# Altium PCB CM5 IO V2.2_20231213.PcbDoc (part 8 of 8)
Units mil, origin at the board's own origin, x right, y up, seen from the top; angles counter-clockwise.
Board outline 6299.61 x 3544.09 mil, 4 copper layers (Top, GND, Power, Bottom), stack 35.4 mil thick; 482 components, 404 nets, 1857 pads, 2731 vias.
Unrouted connection lines stored in the file: 1872.
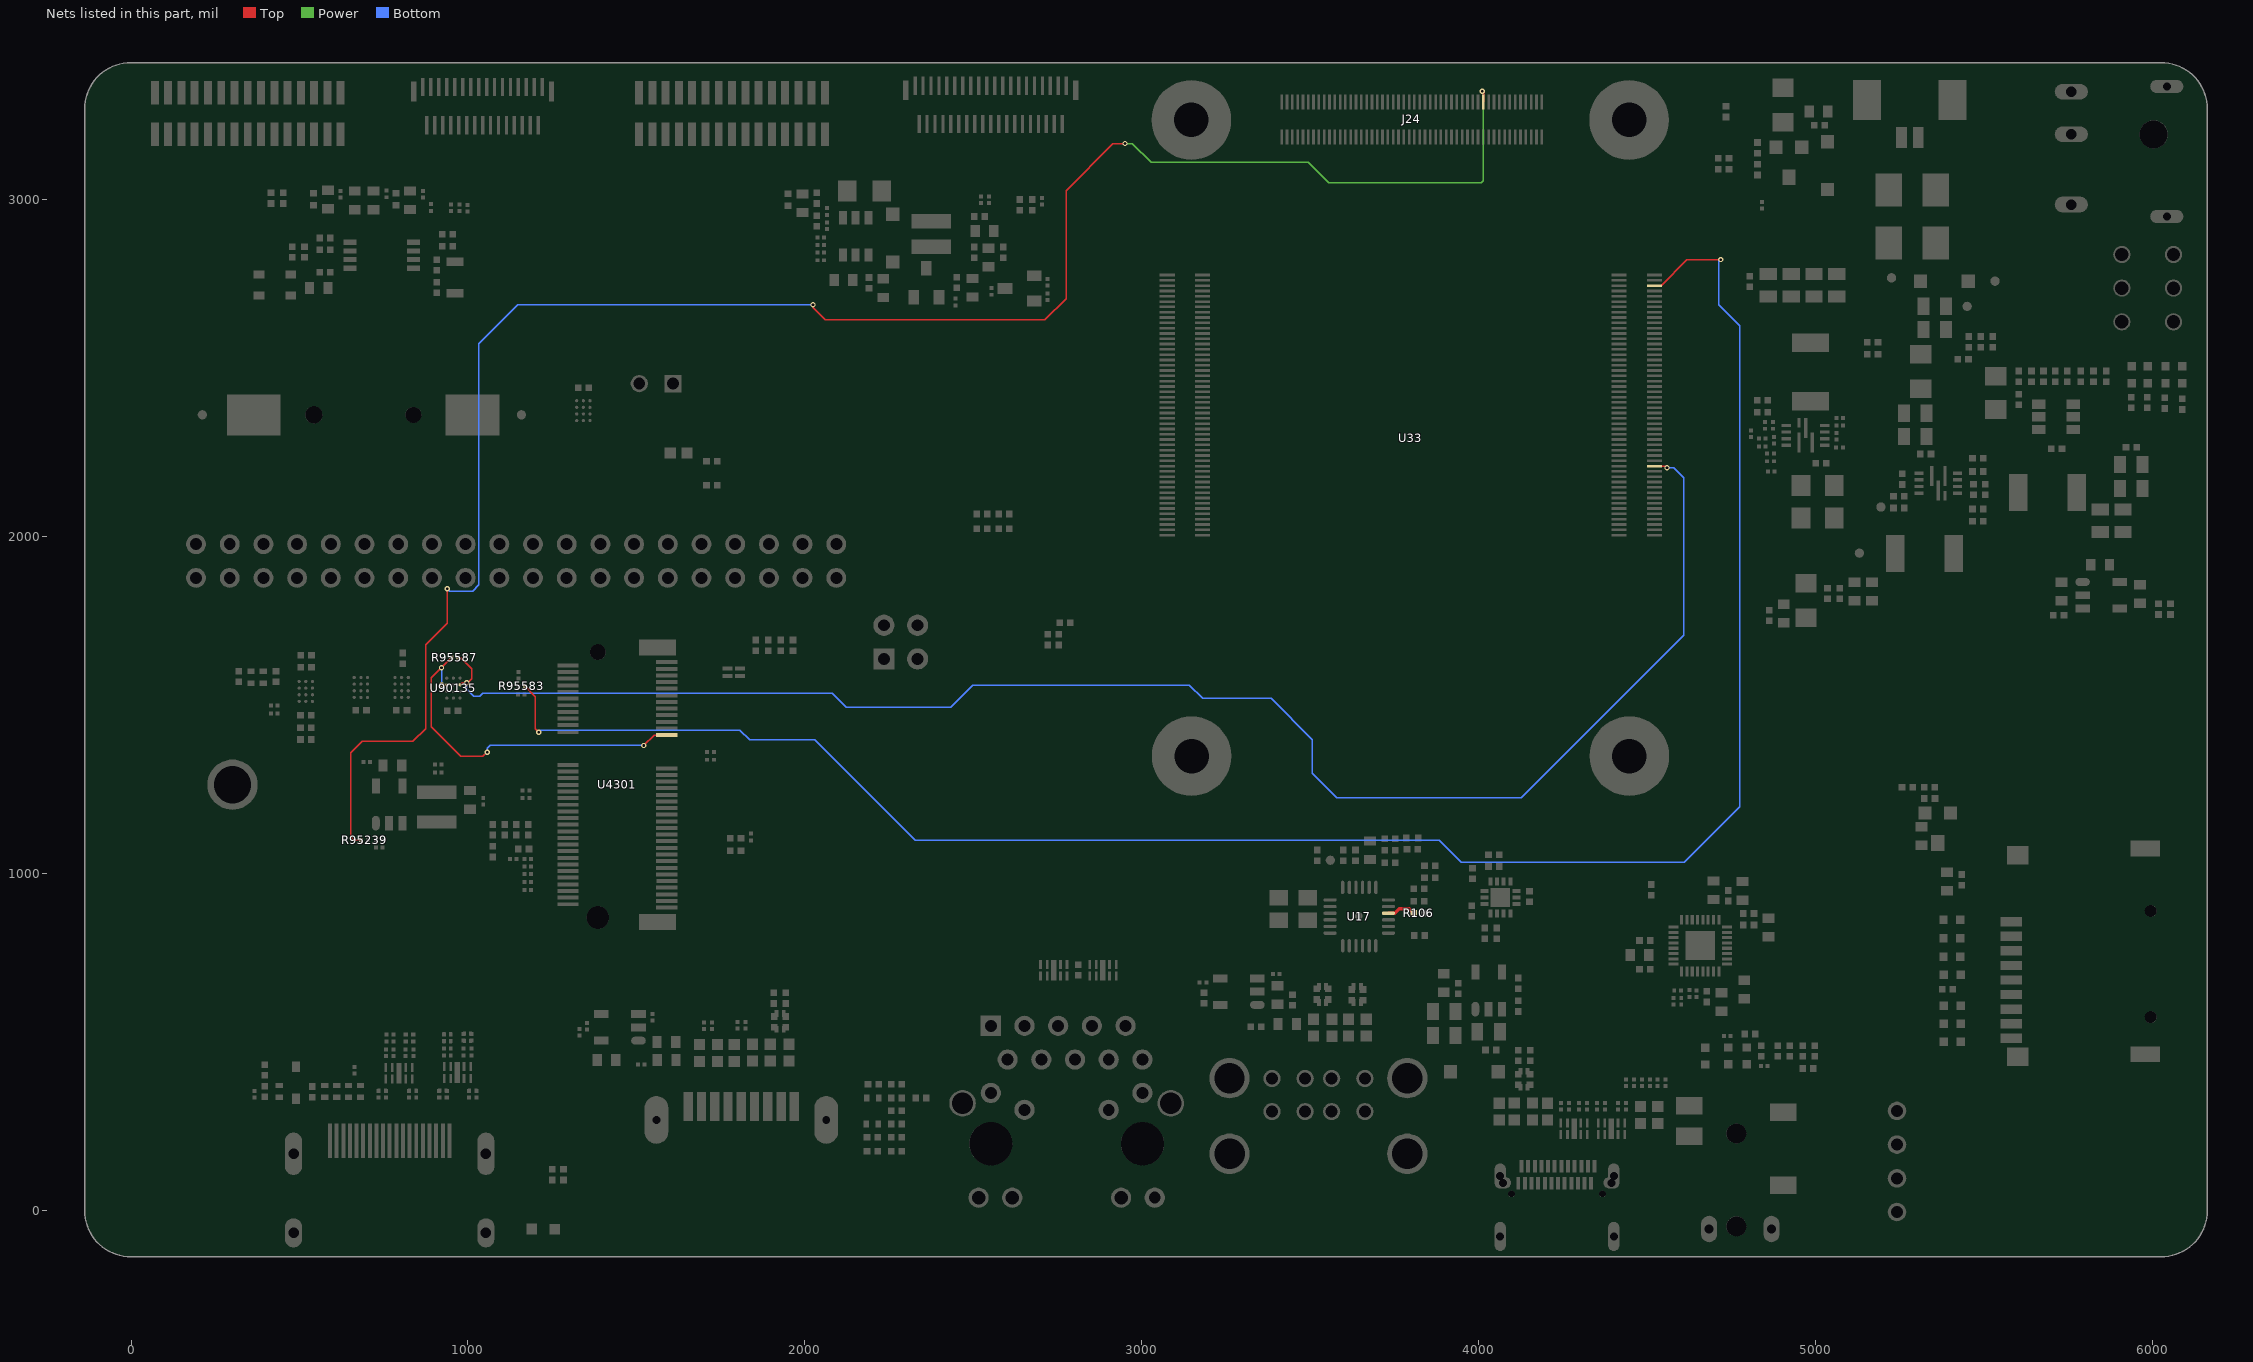
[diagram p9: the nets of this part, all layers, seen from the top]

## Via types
v1: diameter 15.75, hole 7.87, Top to Bottom, 2292 vias
v2: diameter 19.68, hole 11.81, Top to Bottom, 439 vias

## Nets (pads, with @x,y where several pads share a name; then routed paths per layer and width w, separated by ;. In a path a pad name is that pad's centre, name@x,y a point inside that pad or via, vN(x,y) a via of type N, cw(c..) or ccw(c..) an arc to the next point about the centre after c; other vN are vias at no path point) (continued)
WIFI_LED: R95583.1 U33.95 | length 5831.9
  Top w3.94: R95583.1@1169.29,1554.13 1199.8,1523.62 1199.8,1428.15 v1(1209.65,1418.31) ; U33.95@4520.47,2743.5 4540.35,2743.5 4616.73,2819.88 4717.52,2819.88 v1(4717.52,2820.87)
  Bottom w3.94: v1(1209.65,1418.31) 1215.55,1424.21 1807.09,1424.21 1835.63,1395.67 2029.53,1395.67 2327.76,1097.44 3882.87,1097.44 3947.83,1032.48 4609.25,1032.48 4774.61,1197.83 4774.61,2624.02 4711.61,2687.01 4711.61,2814.96 v1(4717.52,2820.87)
WIFI_PWR_EN: J24.24 R95239.1 | length 5608.1
  Top w3.94: R95239.1@683.07,1098.43 662.4,1098.43 652.76,1108.07 652.76,1357.98 686.5,1391.73 836.61,1391.73 874.02,1429.13 874.02,1678.15 937.99,1742.13 v1(937.99,1844.49) ; v1(2023.62,2687.01) 2023.93,2687.32 2023.93,2677.47 2059.67,2641.73 2711.61,2641.73 2774.61,2704.72 2774.61,3025.9 2914.06,3165.35 v1(2949.8,3165.35) ; v1(4009.84,3320.87) 4013.78,3316.93 4013.78,3289.17 J24.24@4013.19,3288.58
  Power w3.94: v1(2949.8,3165.35) 2971.26,3165.35 3027.36,3109.25 3494.04,3109.25 3554.08,3049.21 4006.89,3049.21 4012.8,3055.12 4012.8,3317.91 v1(4009.84,3320.87)
  Bottom w3.94: v1(937.99,1844.49) 945.87,1836.61 1013.78,1836.61 1032.48,1855.31 1032.48,2571.48 1148,2687.01 v1(2023.62,2687.01)
WIFI_REG_ON: R95587.2 U4301.23 U90135.B1 | length 1064.8
  Top w3.94: v1(921.26,1609.25) v1@921.26,1610.24 ; v1(922.24,1559.06) U90135.B1@937.01,1559.05 ; R95587.2@950.79,1639.76 v1@921.26,1610.24 ; v1(1057.09,1359.25) 1044.29,1346.46 978.35,1346.46 890.75,1434.06 890.75,1579.72 v1@921.26,1610.24 ; v1(1521.65,1378.94) 1552.52,1409.8 U4301.23@1589.78,1409.8
  Bottom w3.94: v1(921.26,1609.25) 922.24,1608.27 v1(922.24,1559.06) ; v1(1057.09,1359.25) 1057.09,1370.08 1065.94,1378.94 v1(1521.65,1378.94)
WIFI_REG_ON_E: R95587.1 U33.27 U90135.B3 | length 4783.4
  Top w3.94: R95587.1@970.47,1639.76 978.35,1639.76 1011.81,1606.3 1011.81,1576.77 998.03,1562.99 v1(996.06,1564.96) 982.29,1564.96 U90135.B3@976.38,1559.05 ; U33.27@4520.47,2208.07 4552.76,2208.07 v1(4558.07,2202.76)
  Bottom w3.94: v1(996.06,1564.96) 996.06,1546.26 1016.73,1525.59 1035.43,1525.59 1044.29,1534.45 2080.71,1534.45 2123.03,1492.13 2432.09,1492.13 2498.03,1558.07 3140.44,1558.07 3179.81,1518.7 3383.44,1518.7 3505.91,1396.23 3505.91,1295.95 3578.43,1223.43 4125.11,1223.43 4608.27,1706.58 4608.27,2173.03 4578.54,2202.76 v1(4558.07,2202.76)
XRSTJ: R106.2 U17.16 | length 86
  Top w9.84: U17.16@3731.49,881.2 3750.29,881.2 3763.78,894.68 3792.81,894.68 R106.2@3806.29,881.2
pads on no net: CN14A1.14 CN14A1.15 J3.21 J3.22 J6.16 J6.17 J6.18 J6.19 J6.20 J6.21 J6.22 J6.23 J6.24 J6.25 J6.26 J6.27 J6.28 J6.29 J6.30 J7.16 J7.17 J7.18 J7.19 J7.20 J7.21 J7.22 J7.23 J7.24 J7.25 J7.26 J7.27 J7.28 J7.29 J7.30 J15.1 J15.7 J15.8 J24.16 J24.33 J24.35 J24.39 J24.41 J24.44 J24.46 J24.50 J24.52 J24.54 J24.58 J24.60 J24.64 J24.66 J24.70 J24.78 J24.80 J24.82 J24.84 J24.86 J24.88 J24.91 J24.97 J5002.8 J5002.9 J5002.22 J5002.26 J8202.H1 J8202.H2 U1.4 U17.2 U17.22 U17.23 U17.24 U27.4 U27.12 U33.16 U33.18 U33.26 U33.64 U33.68 U33.70 U33.72 U33.76 U33.78 U33.94 U33.101 U33.104 U33.111 U33.143 U33.146 U33.148 U33.149 U33.152 U33.154 U33.158 U33.160 U33.164 U33.166 U37.6 U4301.8 U4301.9 U4301.10 U4301.11 U4301.12 U4301.13 U4301.14 U4301.15 U4301.16 U4301.17 U4301.19 U4301.22 U4301.32 U4301.34 U4301.36 U4301.38 U4301.40 U4301.44 U4301.46 U4301.48 U4301.59 U4301.61 U4301.62 U4301.64 U4301.65 U4301.66 U4301.67 U4301.68 U4301.71 U4301.73 U4301.78 U4301.79 U90104.5 U90104.36 U90104.37 U90129.11 U90129.29 U90129.30 U90131.3 U90131.4 U90133.D1 U90133.D3 U90135.A1 U90135.A3 U90136.C1 U90136.C3 U90136.D1 U90136.D3

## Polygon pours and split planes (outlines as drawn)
GND on Power (solid, remove dead copper, pour order 10): -163.39,1177.17 -163.39,1139.76 -110.24,1139.76 -110.24,1177.17
VCC5V0_SYS on Power (solid, remove dead copper, pour order 5): 4933.07,2027.56 4933.07,1174.21 4665.35,906.5 3097.44,906.5 2696.6,1307.33 2696.6,2641.73 2591.41,2746.92 2466.54,2746.92 2315.51,2595.9 1871.06,2595.9 1756.61,2710.35 856.3,2710.35 717.87,2848.78 717.87,2941.93 694.07,2965.73 629.92,2965.73 596.86,2932.67 478.35,2932.67 94.49,2548.81 94.49,592.72 433.17,254.04 2172.24,254.04 2213.48,295.28 3724.41,295.28 3728.35,291.34 4375,291.34 4706.19,-39.86 5350.39,-39.86 5435.77,45.52 5435.77,281.5 5776.57,625.39 5776.57,2027.56
VBUS5V0_TYPEC on Power (solid, remove dead copper, pour order 4): 4049.21,25.59 4049.21,-35.79 4286.77,-35.79 4307.79,-14.76 4307.79,15.47 4282.91,40.35 4282.91,59.61 4303.03,79.72 4303.03,156.37 4293.31,166.09 4267.96,166.09 4253.44,151.57 4253.44,38.2 4241.45,26.21 4220.1,26.21 4209.89,36.42 4209.89,141.98 4194.82,157.05 4182.58,157.11 4139.76,115.16 4139.76,42.32 4123.03,25.59
GND on Power (solid, remove dead copper, pour order 3): -235.24,3552.17 -235.24,-220.47 6285.43,-220.47 6285.43,3552.17
VCC3V3_SYS on Power (solid, remove dead copper, pour order 2): 2326.38,2866.14 2325.2,2866.14 2325.2,2785.04 2856.3,2785.04 2856.3,2854.33 2726.77,2983.86 2444.09,2983.86
VCC5V0_USB on Power (solid, remove dead copper, pour order 1): 3104.82,910.43 4664.37,910.43 4930.12,1176.18 4930.12,1758.86 4570.87,1758.86 4570.87,1324.8 4500,1253.94 3123.03,1253.94 3084.15,1215.06 3084.15,931.1
VCC3V3_SYS on Power (solid, remove dead copper, pour order 0): 5884.84,2038.39 5884.84,2382.87 5312.01,2382.87 4742.38,2952.5 3428.41,2952.5 3355.31,2879.41 2336.1,2879.41 2232.24,2775.54 2099.36,2775.54 1770.67,3104.24 494.19,3104.24 465.74,3075.79 465.74,2967.71 484.25,2949.2 597.06,2949.2 621.06,2973.19 704.49,2973.19 731.82,2945.87 731.82,2856.82 869.09,2719.55 1767.78,2719.55 1883.86,2603.47 2318.77,2603.47 2471.46,2756.15 2615.4,2756.15 2684.06,2687.5 3517.22,2687.5 4166.34,2038.39
GND on GND (solid, remove dead copper, pour order 6): -155.51,3423.23 -155.51,-629.92 6181.1,-629.92 6181.1,3423.23
GND on Bottom (solid, remove dead copper, pour order 9): -171.26,3438.98 -171.26,-629.92 6196.85,-629.92 6196.85,3438.98
VBUS5V0_TYPEC on Bottom (solid, remove dead copper, pour order 7): 4049.21,25.59 4049.21,-35.79 4286.77,-35.79 4307.79,-14.76 4307.79,15.47 4282.91,40.35 4282.91,59.61 4303.03,79.72 4303.03,156.37 4293.31,166.09 4267.96,166.09 4253.44,151.57 4253.44,38.2 4241.45,26.21 4220.1,26.21 4209.89,36.42 4209.89,141.98 4194.82,157.05 4182.58,157.11 4139.76,115.16 4139.76,42.32 4123.03,25.59
GND on Top (solid, remove dead copper, pour order 8): -147.64,3415.35 -147.64,-629.92 6173.23,-629.92 6173.23,3415.35

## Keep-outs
Top:
  region: 494.09,1573.82 494.09,1504.92 543.31,1504.92 543.31,1573.82 494.09,1573.82
  region: 3371.06,954.72 3371.06,827.76 3524.61,827.76 3524.61,954.72 3371.06,954.72
  region: 935.04,2827.76 935.04,2707.68 987.2,2707.68 987.2,2827.76 935.04,2827.76
  region: 657.48,1585.63 657.48,1516.73 706.69,1516.73 706.69,1585.63 657.48,1585.63
  region: 4178.15,3263.78 4178.15,3312.01 3420.28,3312.01 3420.28,3263.78 4178.15,3263.78
  region: 2315.94,2956.69 2315.94,2837.6 2434.06,2837.6 2434.06,2956.69 2315.94,2956.69
  region: 4882.87,2553.15 4882.87,2422.24 5082.68,2422.24 5082.68,2553.15 4882.87,2553.15
  region: 3422.24,3208.66 3422.24,3160.43 4178.15,3160.43 4178.15,3208.66 3422.24,3208.66
  region: 5173.23,2971.46 5173.23,2921.26 5412.4,2921.26 5412.4,2971.46 5173.23,2971.46
  region: 4440.94,2009.84 4440.94,2780.51 4390.75,2780.51 4390.75,2009.84 4440.94,2009.84
  region: 932.09,1583.66 932.09,1514.76 981.3,1514.76 981.3,1583.66 932.09,1583.66
  region: 4496.06,2782.48 4496.06,2014.76 4545.28,2014.76 4545.28,2782.48 4496.06,2782.48
  region: 848.43,1256.89 848.43,1150.59 966.54,1150.59 966.54,1256.89 848.43,1256.89
  region: 3051.18,2780.51 3051.18,1996.06 3100.39,1996.06 3100.39,2780.51 3051.18,2780.51
  region: 778.54,1585.63 778.54,1516.73 827.76,1516.73 827.76,1585.63 778.54,1585.63
  region: 5598.43,2230.31 5598.43,2028.54 5794.29,2028.54 5794.29,2230.31 5598.43,2230.31
  region: 1311.02,2413.39 1311.02,2331.69 1373.03,2331.69 1373.03,2413.39 1311.02,2413.39
  region: 3155.51,1995.08 3203.74,1995.08 3203.74,2777.56 3155.51,2777.56 3155.51,1995.08
  region: 5215.55,2050.2 5215.55,1848.43 5429.13,1848.43 5429.13,2050.2 5215.55,2050.2
Power:
  region: 1657.15,1500 ccw(c1645.67,1500) 1645.67,1511.48 ccw(c1645.67,1500) 1634.19,1500 ccw(c1645.67,1500) 1645.67,1488.52 ccw(c1645.67,1500)
  region: 5310.45,2305.12 ccw(c5297.24,2305.12) 5297.24,2318.32 ccw(c5297.24,2305.12) 5284.04,2305.12 ccw(c5297.24,2305.12) 5297.24,2291.91 ccw(c5297.24,2305.12)
Keep-Out Layer:
  lines w3.94: -53.15,-0.79 53.15,-0.79 ; -53.12,1929.12 53.18,1929.12 ; 242.15,177.15 348.45,177.15 ; 242.15,2893.68 348.45,2893.68 ; 2230.34,-0.02 2336.64,-0.02 ; 2230.34,1929.12 2336.64,1929.12 ; 5517.74,177.15 5624.04,177.15 ; 5517.74,2893.68 5624.04,2893.68 ; -137.8,-0.79 ccw(c0,-0.79) 0,-138.58 6024.02,-138.58 ccw(c6024.02,-0.79) 6161.81,-0.79 6161.81,3267.72 ccw(c6024.02,3267.72) 6024.02,3405.51 0,3405.51 ccw(c0,3267.72) -137.8,3267.72 -137.8,-0.79 ; 5971.46,3161.42 6033.46,3161.42 6033.46,3223.43 5971.46,3223.43 5971.46,3161.42

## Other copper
Top:
  region net N43540: 5859.25,3364.17 5529.53,3364.17 5486.22,3320.87 5486.22,3237.2 5383.86,3134.84 5212.6,3134.84 5178.4,3100.64 5178.4,2969.49 5499.02,2969.49 5694.88,3165.35 5694.88,3211.61 5717.77,3234.5 5859.25,3234.5 5859.25,3364.17
  region net VCC_SYSIN: 4778.54,2591.54 4778.54,2614.17 4749.02,2614.17 4749.02,2584.15 4755.41,2584.15 4762.8,2591.54 4778.54,2591.54
  region net VCC5V0_USB: 3153.54,625 3153.54,559.06 3257.87,559.06 3257.87,625 3153.54,625
  region net VCC3V3_SYS: 5750,2245.08 5750,2040.35 5932.09,2040.35 5932.09,2274.61 5779.53,2274.61 5750,2245.08
  region net GND: 3360.24,913.39 3407.48,913.39 3407.48,923.23 3360.24,923.23 3360.24,913.39
  region net N42228: 5361.22,2150.59 5329.23,2118.6 5329.23,2043.31 5369.83,2002.71 5369.83,1849.41 5476.38,1849.41 5490.16,1863.19 5490.16,2018.7 5467.52,2041.34 5467.52,2042.32 5441.44,2068.41 5441.44,2083.66 5429.87,2095.23 5374.02,2095.23 5365.53,2103.72 5365.53,2150.59 5361.22,2150.59
  region net VCC_LEDA: 2322.83,3270.67 2322.83,3160.43 2343.5,3160.43 2343.5,3250 2322.83,3270.67
  region net VCC5V0_SYS: 3874.02,728.35 3874.02,669.29 4000,669.29 4000,728.35 3874.02,728.35
  region net VCC5V0_SYS: 4050.2,1064.96 4050.2,1045.28 4106.3,1045.28 4106.3,1064.96 4050.2,1064.96
  region net VCC5V0_SYS: 2381.89,2698.82 2526.57,2698.82 2526.57,2743.11 2381.89,2743.11 2381.89,2698.82
  region net VCC_3V3_S3: 5070.87,2902.56 5097.44,2875.98 5103.35,2875.98 5124.02,2896.65 5124.02,2906.5 5099.41,2931.1 5070.87,2902.56
  region net N132478: 716.54,1269.68 709.65,1262.8 709.65,1254.92 717.03,1247.54 730.31,1247.54 730.31,1269.68 716.54,1269.68
  region net VCC5V0_SYS: 4876.97,2185.04 4825.3,2133.37 4825.3,1875 4863.44,1836.86 4958.66,1836.86 4958.66,2186.02 4876.97,2186.02 4876.97,2185.04
  region net VCC3V3_WF: 1375,1397.64 1354.33,1376.97 1354.33,1345.47 1371.56,1328.25 1399.61,1328.25 1399.61,1397.64 1375,1397.64
  region net VCC12V: 5292.57,2486.22 5292.57,2291.58 5356.79,2227.36 5356.79,2189.47 5380.91,2165.35 5380.91,2157.48 5398.5,2157.48 5398.5,2194.02 5408.46,2203.99 5438.73,2203.99 5502.95,2268.21 5560.53,2268.21 5635.83,2343.5 5679.13,2343.5 5679.13,2367.25 5638.9,2367.25 5603.35,2402.81 5521.9,2402.81 5483.76,2440.94 5483.76,2465.06 5462.6,2486.22 5292.57,2486.22
  region net VCC_MIPI: 1940.55,3004.72 2053.54,3004.72 2053.54,3042.91 1957.09,3042.91 1940.55,3026.38 1940.55,3004.72
  region net OVCJ: 3545.28,922.24 3545.28,918.31 3570.62,918.31 3570.62,922.98 3562.99,930.61 3553.64,930.61 3545.28,922.24
  region net VCC5V0_USB1: 1679.13,331.69 1679.13,243.11 1689.96,232.28 1696.85,232.28 1711.12,246.56 1711.12,257.87 1706.94,262.06 1706.94,331.69 1679.13,331.69
  region net VCC5V0_USB: 1325.79,519.68 1325.79,423.23 1408.46,423.23 1408.46,519.68 1325.79,519.68
  region net GND: 3497.05,861.22 3497.05,821.85 3506.89,821.85 3506.89,861.22 3497.05,861.22
  region net N16722445: 2176.18,2771.65 2176.18,2751.97 2199.8,2751.97 2199.8,2771.65 2176.18,2771.65
  region net VBUS5V0_TYPEC: 3850.39,458.66 3862.2,446.85 3872.05,446.85 3872.05,463.58 3850.39,463.58 3850.39,458.66
  region net VCC5V0_USB1: 1490.16,509.84 1490.16,467.52 1524.11,433.56 1563.98,433.56 1563.98,509.84 1490.16,509.84
  region net N43676: 5634.72,2323.82 5557.95,2247.05 5557.95,2033.34 5568.9,2022.39 5631.15,2022.39 5655.02,2046.26 5655.02,2212.11 5699.8,2256.89 5699.8,2323.82 5634.72,2323.82
  region net VCC5V0_SYS: 5169.29,2066.93 5162.4,2066.93 5162.4,2029.53 5184.55,2029.53 5184.55,2051.67 5169.29,2066.93
  region net N28976: 3691.93,941.93 3736.22,941.93 3762.8,968.5 3762.8,1091.54 3795.28,1091.54 3795.28,1121.06 3736.22,1121.06 3736.22,1011.81 3691.93,967.52 3691.93,941.93
  region net VCC5V0_USB: 3101.57,967.72 3056.69,967.72 3056.69,613.78 3120.47,550 3251.97,550 3251.97,616.54 3144.49,616.54 3101.57,659.45 3101.57,967.72
  region net VCC5V0_SYS: 4933.56,2301.18 4933.56,2260.33 4898.62,2225.39 4898.62,2213.58 4876.97,2191.93 4876.97,1835.63 5263.78,1835.63 5263.78,2055.73 5174.58,2055.73 5130.91,2012.06 5021.9,2012.06 5009.35,2024.61 5009.35,2210.14 4975.39,2244.09 4975.39,2279.53 4960.63,2279.53 4949.8,2290.35 4949.8,2301.18 4933.56,2301.18
  region net VCC_3V3_S3: 5293.31,1122.05 5368.11,1122.05 5368.11,1163.39 5337.11,1194.39 5293.31,1194.39 5293.31,1122.05
  region net VCC5V0_SYS: 641.73,2984.25 641.73,2937.01 682.09,2937.01 682.09,2984.25 641.73,2984.25
  region net VCC3V3_SYS: 520.67,2993.11 520.67,2952.76 554.13,2952.76 554.13,2993.11 520.67,2993.11
  region net VCC5V0_SYS: 4050.2,1064.96 4050.2,1004.92 4078.74,1004.92 4078.74,1064.96 4050.2,1064.96
  region net VCC_3V3_S0: 5731.3,1919.29 5731.3,1854.33 5830.71,1854.33 5830.71,1919.29 5731.3,1919.29
  region net VCC5V0_USB: 3812.01,1114.17 3812.01,1044.29 3850.39,1044.29 3850.39,1114.17 3812.01,1114.17
  region net VCC5V0_USB: 3077.76,968.11 3077.76,911.42 3180.12,911.42 3180.12,968.11 3077.76,968.11
  region net N16763522: 3321.11,624.02 3321.11,578.99 3346.95,553.15 3346.95,462.11 3369.09,439.96 3397.64,439.96 3434.06,476.38 3434.06,576.77 3455.71,598.43 3455.71,624.02 3321.11,624.02
  region net VCC3V3_SD: 5382.87,1113.19 5288.39,1113.19 5288.39,930.12 5456.69,930.12 5456.69,975.39 5350.39,975.39 5350.39,1051.18 5382.87,1051.18 5382.87,1113.19
  region net VCC12V: 5466.54,2490.16 5456.69,2490.16 5456.69,2466.54 5466.54,2466.54 5466.54,2490.16
  region net VCC3V3_WF: 1134.84,1279.53 1154.53,1279.53 1160.43,1285.43 1160.43,1302.17 1134.84,1302.17 1134.84,1279.53
  region net VCC5V0_SYS: 790.35,1342.52 790.35,1289.37 864.17,1289.37 864.17,1342.52 790.35,1342.52
  region net N132294: 802.17,1170.28 802.17,1126.97 966.54,1126.97 966.54,1170.28 802.17,1170.28
  region net VCC5V0_SYS: 5017.72,3278.54 5017.72,3195.87 5079.72,3195.87 5079.72,3278.54 5017.72,3278.54
  region net N16734501: 4966.78,2315.94 5004.92,2315.94 5004.92,2334.65 5037.4,2367.13 5096.46,2367.13 5096.46,2428.15 4859.25,2428.15 4859.25,2400.59 4895.18,2364.67 4950.79,2364.67 4966.78,2348.67 4966.78,2315.94
  region net VCC_3V3_S3: 5858.27,1921.26 5858.27,1835.63 6046.26,1835.63 6046.26,1921.26 5858.27,1921.26
  region net VCC_SYSIN: 5105.81,2668.31 5105.81,2680.61 5099.41,2687.01 5062.01,2687.01 5062.01,2657.48 5082.68,2657.48 5093.5,2668.31 5105.81,2668.31
  region net VCC3V3_SYS: 771.65,2992.13 771.65,2955.71 800.2,2955.71 800.2,2992.13 771.65,2992.13
  region net VCC5V0_USB: 4839.57,1760.83 4839.57,1669.29 5001.97,1669.29 5001.97,1760.83 4839.57,1760.83
  region net VCC3V3_SYS: 2578.74,2837.6 2578.74,2815.94 2632.87,2815.94 2632.87,2837.6 2578.74,2837.6
  region net VCC3V3_SYS: 1918.31,2990.16 1918.31,2900.59 1959.65,2900.59 1959.65,2990.16 1918.31,2990.16
  region net 3V3_CAM1: 530.76,3007.87 599.41,3007.87 610.24,3018.7 637.8,3018.7 637.8,3227.36 614.17,3227.36 614.17,3065.94 601.87,3053.64 545.28,3053.64 530.76,3039.12 530.76,3007.87
  region net VCC_SYSIN: 4548.23,2678.15 4548.23,2599.41 4765.75,2599.41 4814.96,2550.2 5085.63,2550.2 5085.63,2741.63 4611.71,2741.63 4548.23,2678.15
  region net 5V_CAM: 648.62,3046.26 648.62,3010.64 735.42,3010.64 746.06,3021.28 758.24,3021.28 789.37,3052.41 860.97,3052.41 879.43,3070.87 879.43,3262.3 868.11,3273.62 860.97,3273.62 860.97,3082.92 850.39,3072.34 762.3,3072.34 736.22,3046.26 648.62,3046.26
  region net VCC_3V3_S0: 5661.42,1900.59 5661.42,1852.36 5811.02,1852.36 5811.02,1900.59 5661.42,1900.59
  region net VCC12V_DCIN: 5173.23,2923.23 5173.23,2497.05 5430.12,2497.05 5430.12,2571.85 5357.28,2571.85 5357.28,2726.38 5413.88,2782.97 5413.88,2923.23 5173.23,2923.23
  region net VCC_SYSIN: 4552.17,2601.38 4581.69,2571.85 4645.67,2571.85 4664.86,2552.66 4853.35,2552.66 4853.35,2672.24 4553.15,2672.24 4553.15,2601.38 4552.17,2601.38
  region net VBUS5V0_TYPEC: 3900.1,618.11 3888.29,606.3 3888.29,487.7 3862.2,461.61 3862.2,53.15 3942.91,-27.56 4107.28,-27.56 4107.28,23.38 4088.34,23.38 4024.11,87.6 4024.11,503.44 4000,527.56 4000,618.11 3900.1,618.11
  text "160.1mm" at 2850.6,3545.18 h50
  text "90.0mm" at -546.26,1590.55 h50
Power:
  region net VCC12V: 5339.07,2489.17 5339.07,2450.3 5378.94,2410.43 5484.25,2410.43 5484.25,2489.17 5339.07,2489.17
  region net VCC_1V8_S0: 4943.9,2906.5 4943.9,2863.19 4980.31,2863.19 4980.31,2906.5 4943.9,2906.5
  region net VCC3V3_SYS: 4908.66,2772.44 4908.66,2737.01 4943.7,2737.01 4943.7,2765.75 4937.01,2772.44 4908.66,2772.44
  region net VCC5V0_SYS: 4169.29,901.57 4162.89,907.97 4153.54,907.97 4147.88,902.31 4147.88,896.65 4169.29,896.65 4169.29,901.57
  region net VCC_1V8_S3: 97.44,2634.84 97.44,2642.72 103.35,2648.62 103.35,2653.54 89.57,2653.54 89.57,2634.84 97.44,2634.84
Bottom:
  region net VCC5V0_SYS: 4937.01,1969.49 4937.01,1882.87 5112.2,1882.87 5112.2,1969.49 4937.01,1969.49
  region net VCC3V3_SYS: 5818.9,2203.74 5818.9,2117.13 5880.91,2117.13 5880.91,2203.74 5818.9,2203.74
  region net VCC5V0_SYS: 5031.5,3244.09 5031.5,3195.87 5079.72,3195.87 5079.72,3244.09 5031.5,3244.09
  region net VCC3V3_SYS: 1045.28,2834.65 1045.28,2781.5 1091.54,2781.5 1091.54,2834.65 1045.28,2834.65
  region net VCC_3V3_S3: 5974.41,1910.43 5974.41,1837.6 6041.34,1837.6 6041.34,1910.43 5974.41,1910.43
  region net VCC5V0_USB: 1326.38,471.65 1326.38,420.08 1376.77,420.08 1376.77,471.65 1326.38,471.65
  region net VCC5V0_USB: 3084.65,947.83 3084.65,902.56 3179.63,902.56 3179.63,919.78 3151.57,947.83 3084.65,947.83
  region net VCC5V0_USB1: 1669.29,263.78 1669.29,213.39 1716.93,213.39 1716.93,263.78 1669.29,263.78
  region net VCC_3V3_S3: 5067.91,2905.51 5096.46,2876.97 5111.22,2876.97 5125.98,2891.73 5128.94,2888.78 5128.94,2927.17 5067.91,2927.17 5067.91,2905.51
  region net VCC5V0_USB1: 1500.39,481.1 1500.39,430.31 1553.94,430.31 1553.94,481.1 1500.39,481.1
  region net VCC_3V3_S3: 5064.96,911.42 5064.96,883.86 5113.19,883.86 5113.19,911.42 5064.96,911.42
  region net VCC_3V3_S3: 5395.67,1161.42 5346.46,1161.42 5324.8,1139.76 5324.8,1109.25 5346.46,1109.25 5363.19,1125.98 5395.67,1125.98 5395.67,1161.42
  region net VCC5V0_USB: 3090.55,940.94 3063.48,913.88 3063.48,896.65 3110.24,896.65 3110.24,940.94 3090.55,940.94
Multi-Layer:
  lines w1: 80.71,-137.8 80.74,-137.8 ; 6161.42,3255.91 6161.44,3255.91 ; -139.76,3370.08 -139.74,3370.08 ; 62.99,3405.51 63.02,3405.51
  lines w10: -337.4,-137.8 30.71,-137.8 ; -337.4,3405.51 12.99,3405.51 ; -287.4,1560.55 -287.4,-137.8 ; -287.4,1695.55 -287.4,3405.51 ; -139.76,3420.08 -139.76,3632.68 ; 2820.6,3582.68 -139.76,3582.68 ; 3201.05,3582.68 6161.42,3582.68 ; 6161.42,3305.91 6161.42,3632.68 ; -287.4,-137.8 -262.4,-37.8 -312.4,-37.8 -287.4,-137.8 ; -287.4,3405.51 -312.4,3305.51 -262.4,3305.51 -287.4,3405.51 ; -139.76,3582.68 -39.76,3557.68 -39.76,3607.68 -139.76,3582.68 ; 6161.42,3582.68 6061.42,3607.68 6061.42,3557.68 6161.42,3582.68

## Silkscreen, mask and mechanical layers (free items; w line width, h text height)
Silkscreen Top:
  drawing of 22474 lines, arcs and shapes, not listed
  text "FAN" at 5015.75,3307.09 h23.62
  text "12V_DC" at 5550.2,3190.94 h23.62
  text "LCD1" at 2530.51,3119.09 h29.53
  text "Connector3" at 3690.94,3110.24 h23.62
  text "Camera 1" at 936.02,3101.38 h29.53
  text "-" at 5204.72,3094.49 h39.37
  text "+" at 5338.58,3094.49 h39.37
  text "Camera 0" at 164.37,3073.82 h29.53
  text "LCD0" at 1636.81,3064.96 h29.53
  text "Power" at 6013.78,2895.67 h23.62
  text "RECOVERY" at 5628.94,2828.74 h23.62
  text "CM5 IO V2.2" at 1205.71,2752.95 h49.21
  text "GND" at 5558.07,2743.11 h23.62
  text "GND" at 5773.62,2717.52 h23.62
  text "VCC12V" at 5147.64,2700.79 h23.62
  text "BAT_RTC" at 694.88,2684.06 h23.62
  text "GND" at 5474.41,2665.35 h23.62
  text "RESET" at 5724.41,2615.16 h23.62
  text "Maskrom" at 5985.24,2545.28 h23.62
  text "Connector1" at 4342.52,2368.11 h23.62 r90
  text "-MIC+" at 1500,2356.3 h23.62
  text "Connector2" at 3273.62,2352.36 h23.62 r90
  text "GND" at 1190.94,2341.54 h23.62
  text "RTC+" at 175.2,2296.26 h23.62
  text "LDO5V" at 5171.26,2238.19 h23.62 r270
  text "GND" at 409.45,2017.72 h23.62 r90
  text "TX" at 505.91,2017.72 h23.62 r90
  text "RX" at 604.33,2017.72 h23.62 r90
  text "U33-A" at 4377.95,1909.45 h29.53
  text "U33-B" at 3061.02,1895.67 h29.53
  text "VCC5V" at 5056.1,1893.7 h23.62
  text "POE" at 2253.94,1530.51 h29.53
  text "J2" at 276.77,1108.66 h29.53
  text "Ethernet" at 2466.54,647.64 h23.62
  text "USB2.0" at 3306.1,476.38 h29.53
  text "USB3.0" at 1992.13,377.95 h23.62
  text "Ext_PSU" at 5165.35,372.05 h23.62
  text "SD-CARD" at 5617.13,358.27 h29.53
  text "12V" at 5368.11,279.53 h23.62
  text "HDMI" at 717.52,273.62 h29.53
  text "TYPE-C" at 4003.94,182.09 h29.53
  text "GND" at 5368.11,177.17 h23.62
  text "GND" at 5368.11,76.77 h23.62
  text "5V" at 5379.92,-19.69 h23.62
Paste Mask Top:
  region: 375.45,1262.6 ccw(c301.18,1262.6) 301.18,1336.87 ccw(c301.18,1262.6) 226.91,1262.6 ccw(c301.18,1262.6) 301.18,1188.33 ccw(c301.18,1262.6)
Layer_103:
  drawing of 25203 lines, arcs and shapes, not listed
Layer_104:
  lines w1: 2368.11,622.05 2368.11,3393.7 5251.97,3393.7 5251.97,622.05 2368.11,622.05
